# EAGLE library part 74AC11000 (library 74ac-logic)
Quadruple 2-input NAND
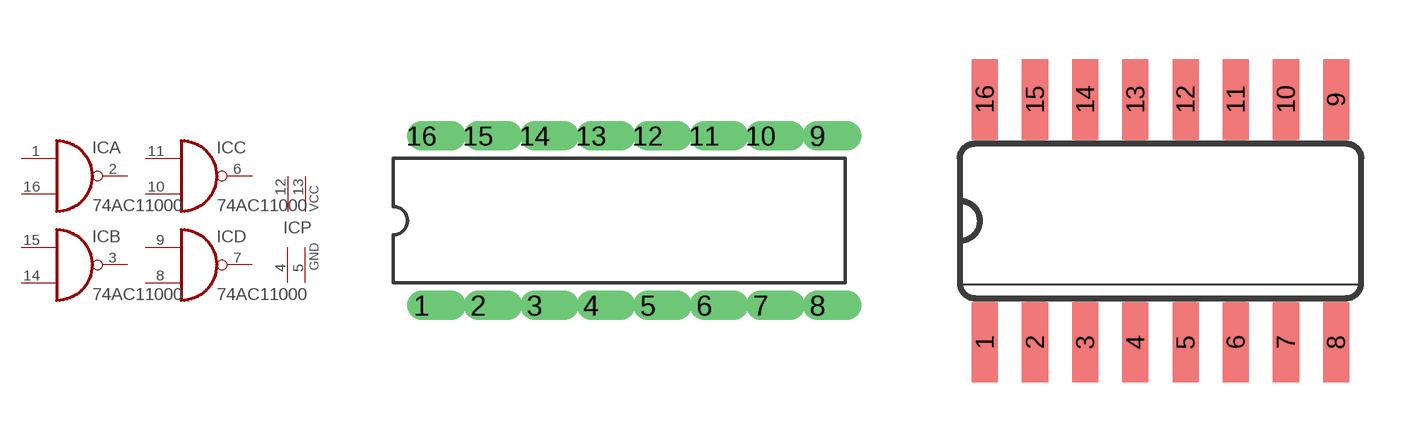
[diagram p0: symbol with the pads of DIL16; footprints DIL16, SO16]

Designator prefix IC; gates A=7411000 B=7411000 C=7411000 D=7411000 P=2PWR2GND

## 74AC11000  [DIL16]
1  A:I0  in
2  A:O  out
3  B:O  out
4  P:GND  pwr
5  P:GND  pwr
6  C:O  out
7  D:O  out
8  D:I1  in
9  D:I0  in
10  C:I1  in
11  C:I0  in
12  P:VCC  pwr
13  P:VCC  pwr
14  B:I1  in
15  B:I0  in
16  A:I1  in

## 74AC11000D  [SO16]
Pads as for DIL16

## Footprint DIL16 (pad centres in mm)
Dual In Line
drill 0.813 offset: 1 -8.89,-3.81; 2 -6.35,-3.81; 3 -3.81,-3.81; 4 -1.27,-3.81; 5 1.27,-3.81; 6 3.81,-3.81; 7 6.35,-3.81; 8 8.89,-3.81; 9 8.89,3.81; 10 6.35,3.81; 11 3.81,3.81; 12 1.27,3.81; 13 -1.27,3.81; 14 -3.81,3.81; 15 -6.35,3.81; 16 -8.89,3.81

## Footprint SO16 (pad centres in mm)
Small Outline package 150 mil
smd 0.66 x 2.032: 1 -4.445,-3.073; 2 -3.175,-3.073; 3 -1.905,-3.073; 4 -0.635,-3.073; 5 0.635,-3.073; 6 1.905,-3.073; 7 3.175,-3.073; 8 4.445,-3.073; 9 4.445,3.073; 10 3.175,3.073; 11 1.905,3.073; 12 0.635,3.073; 13 -0.635,3.073; 14 -1.905,3.073; 15 -3.175,3.073; 16 -4.445,3.073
